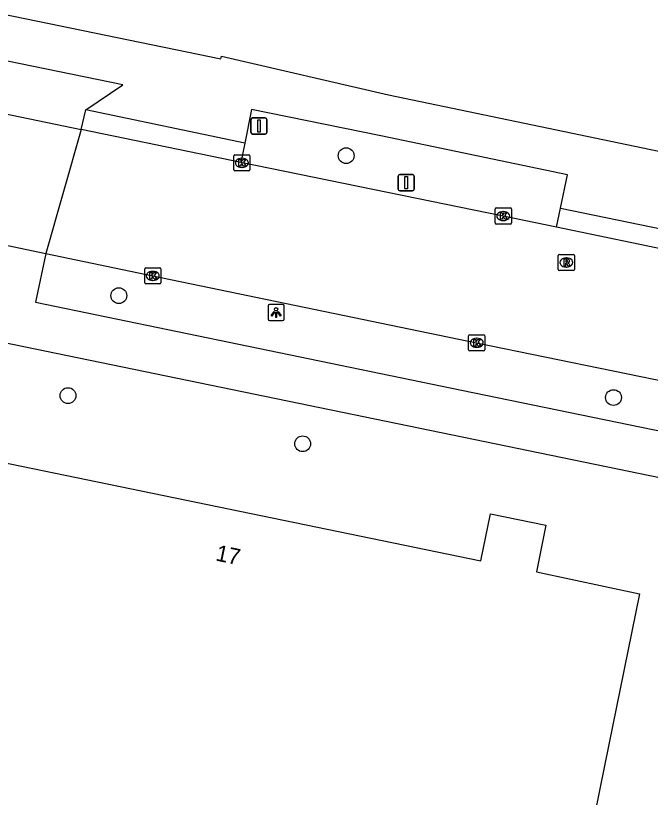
# Model space of a CAD drawing. Extents: x 157692 to 159670, y 381454 to 383289.
# Drawn here: x 158298.36 to 158337.61, y 382496.74 to 382545.08 of the extents above; entities that cross this region are included whole.
import ezdxf

# ---------------------------------------------------------------- set-up
doc = ezdxf.new("R2010")
doc.units = 0
for name, color, linetype in [('IMGEO_Boom', 7, 'Continuous'), ('IMGEO_Kolk', 7, 'Continuous'), ('IMGEO_Lichtpunt', 7, 'Continuous'), ('IMGEO_Pand', 7, 'Continuous'), ('IMGEO_Pand_nummerreeks', 7, 'Continuous'), ('IMGEO_Rijbaan_lokaal_gesloten', 7, 'Continuous'), ('IMGEO_Rioolput', 7, 'Continuous'), ('IMGEO_Verkeersbordpaal', 7, 'Continuous'), ('IMGEO_Voetpad_open', 7, 'Continuous')]:
    doc.layers.add(name, color=color, linetype=linetype)

msp = doc.modelspace()

# ---------------------------------------------------------------- linework, layer by layer
at = {"layer": 'IMGEO_Boom'}
for centre in [(158318.796, 382536.419), (158304.747, 382527.763), (158301.599, 382521.583), (158335.33, 382521.46), (158316.11, 382518.605)]:
    msp.add_circle(centre, 0.489, dxfattribs=at)
at = {"layer": 'IMGEO_Kolk'}
for p, q in [((158311.85, 382535.551), (158311.85, 382536.403)), ((158311.925, 382536.477), (158312.777, 382536.477)), ((158312.338, 382536.257), (158312.363, 382536.257)), ((158312.851, 382536.403), (158312.851, 382535.551)), ((158312.361, 382535.697), (158312.336, 382535.697)), ((158312.777, 382535.477), (158311.925, 382535.477)), ((158328.086, 382533.186), (158328.938, 382533.186)), ((158328.011, 382532.26), (158328.011, 382533.112)), ((158328.499, 382532.966), (158328.524, 382532.966)), ((158329.012, 382533.112), (158329.012, 382532.26)), ((158328.938, 382532.186), (158328.086, 382532.186)), ((158328.522, 382532.406), (158328.497, 382532.406)), ((158306.343, 382528.56), (158306.343, 382529.412)), ((158306.418, 382529.486), (158307.27, 382529.486)), ((158307.344, 382529.412), (158307.344, 382528.56)), ((158306.831, 382529.266), (158306.856, 382529.266)), ((158307.27, 382528.486), (158306.418, 382528.486)), ((158306.854, 382528.706), (158306.829, 382528.706)), ((158326.37, 382524.423), (158326.37, 382525.275)), ((158326.445, 382525.349), (158327.297, 382525.349)), ((158326.858, 382525.129), (158326.883, 382525.129)), ((158327.371, 382525.275), (158327.371, 382524.423)), ((158326.881, 382524.569), (158326.856, 382524.569)), ((158327.297, 382524.349), (158326.445, 382524.349))]:
    msp.add_line(p, q, dxfattribs=at)
for points in [[(158311.85, 382535.551), (158311.85, 382536.403)], [(158311.925, 382536.477), (158312.777, 382536.477)], [(158312.171, 382536.177), (158312.294, 382536.177), (158312.294, 382536.026), (158312.424, 382536.177), (158312.588, 382536.177), (158312.442, 382536.026), (158312.595, 382535.777), (158312.443, 382535.777), (158312.358, 382535.941), (158312.294, 382535.874), (158312.294, 382535.777), (158312.171, 382535.777), (158312.171, 382536.177)], [(158312.851, 382536.403), (158312.851, 382535.551)], [(158312.777, 382535.477), (158311.925, 382535.477)], [(158328.086, 382533.186), (158328.938, 382533.186)], [(158328.011, 382532.26), (158328.011, 382533.112)], [(158328.332, 382532.886), (158328.455, 382532.886), (158328.455, 382532.735), (158328.585, 382532.886), (158328.749, 382532.886), (158328.603, 382532.735), (158328.756, 382532.486), (158328.604, 382532.486), (158328.519, 382532.65), (158328.455, 382532.583), (158328.455, 382532.486), (158328.332, 382532.486), (158328.332, 382532.886)], [(158329.012, 382533.112), (158329.012, 382532.26)], [(158328.938, 382532.186), (158328.086, 382532.186)], [(158306.343, 382528.56), (158306.343, 382529.412)], [(158306.418, 382529.486), (158307.27, 382529.486)], [(158307.344, 382529.412), (158307.344, 382528.56)], [(158306.664, 382529.186), (158306.787, 382529.186), (158306.787, 382529.035), (158306.917, 382529.186), (158307.081, 382529.186), (158306.935, 382529.035), (158307.088, 382528.786), (158306.936, 382528.786), (158306.851, 382528.95), (158306.787, 382528.883), (158306.787, 382528.786), (158306.664, 382528.786), (158306.664, 382529.186)], [(158307.27, 382528.486), (158306.418, 382528.486)], [(158326.37, 382524.423), (158326.37, 382525.275)], [(158326.445, 382525.349), (158327.297, 382525.349)], [(158326.691, 382525.049), (158326.814, 382525.049), (158326.814, 382524.898), (158326.944, 382525.049), (158327.108, 382525.049), (158326.962, 382524.898), (158327.115, 382524.649), (158326.963, 382524.649), (158326.878, 382524.813), (158326.814, 382524.746), (158326.814, 382524.649), (158326.691, 382524.649), (158326.691, 382525.049)], [(158327.371, 382525.275), (158327.371, 382524.423)], [(158327.297, 382524.349), (158326.445, 382524.349)]]:
    msp.add_lwpolyline(points, dxfattribs=at)
for centre, start, end in [((158311.927, 382536.401), 91.552, 178.448), ((158311.927, 382536.401), 91.552, 178.448), ((158312.775, 382536.401), 1.552, 88.448), ((158312.775, 382536.401), 1.552, 88.448), ((158311.927, 382535.553), 181.552, 268.448), ((158311.927, 382535.553), 181.552, 268.448), ((158312.775, 382535.553), 271.552, 358.448), ((158312.775, 382535.553), 271.552, 358.448), ((158328.088, 382533.11), 91.552, 178.448), ((158328.088, 382533.11), 91.552, 178.448), ((158328.936, 382533.11), 1.552, 88.448), ((158328.936, 382533.11), 1.552, 88.448), ((158328.088, 382532.262), 181.552, 268.448), ((158328.088, 382532.262), 181.552, 268.448), ((158328.936, 382532.262), 271.552, 358.448), ((158328.936, 382532.262), 271.552, 358.448), ((158306.42, 382529.41), 91.552, 178.448), ((158306.42, 382529.41), 91.552, 178.448), ((158307.268, 382529.41), 1.552, 88.448), ((158307.268, 382529.41), 1.552, 88.448), ((158306.42, 382528.562), 181.552, 268.448), ((158306.42, 382528.562), 181.552, 268.448), ((158307.268, 382528.562), 271.552, 358.448), ((158307.268, 382528.562), 271.552, 358.448), ((158326.447, 382525.273), 91.552, 178.448), ((158326.447, 382525.273), 91.552, 178.448), ((158327.295, 382525.273), 1.552, 88.448), ((158327.295, 382525.273), 1.552, 88.448), ((158326.447, 382524.425), 181.552, 268.448), ((158326.447, 382524.425), 181.552, 268.448), ((158327.295, 382524.425), 271.552, 358.448), ((158327.295, 382524.425), 271.552, 358.448)]:
    msp.add_arc(centre, 0.0765, start, end, dxfattribs=at)
for centre, major_axis, ratio, start_param, end_param in [((158312.337, 382535.977), (-0.387, 0.002), 0.722429, 4.712389, 7.853982), ((158312.362, 382535.977), (-0.39, 0.002), 0.717154, 1.570796, 4.712389), ((158328.498, 382532.686), (-0.387, 0.002), 0.722429, 4.712389, 7.853982), ((158328.523, 382532.686), (-0.39, 0.002), 0.717154, 1.570796, 4.712389), ((158306.83, 382528.986), (-0.387, 0.002), 0.722429, 4.712389, 7.853982), ((158306.855, 382528.986), (-0.39, 0.002), 0.717154, 1.570796, 4.712389), ((158326.857, 382524.849), (-0.387, 0.002), 0.722429, 4.712389, 7.853982), ((158326.882, 382524.849), (-0.39, 0.002), 0.717154, 1.570796, 4.712389)]:
    msp.add_ellipse(centre, major_axis=major_axis, ratio=ratio, start_param=start_param, end_param=end_param, dxfattribs=at)
at = {"layer": 'IMGEO_Lichtpunt'}
for p, q in [((158313.969, 382527.125), (158313.969, 382526.318)), ((158313.969, 382527.125), (158313.969, 382526.318)), ((158314.871, 382527.22), (158314.063, 382527.22)), ((158314.871, 382527.22), (158314.063, 382527.22)), ((158314.965, 382526.318), (158314.965, 382527.125)), ((158314.965, 382526.318), (158314.965, 382527.125)), ((158314.063, 382526.224), (158314.871, 382526.224)), ((158314.063, 382526.224), (158314.871, 382526.224))]:
    msp.add_line(p, q, dxfattribs=at)
for points in [[(158314.343, 382526.789), (158314.382, 382526.761), (158314.194, 382526.499), (158314.156, 382526.526), (158314.343, 382526.789)], [(158314.445, 382526.741), (158314.492, 382526.741), (158314.492, 382526.419), (158314.445, 382526.419), (158314.445, 382526.741)], [(158314.555, 382526.761), (158314.593, 382526.788), (158314.78, 382526.526), (158314.741, 382526.498), (158314.555, 382526.761)]]:
    msp.add_lwpolyline(points, dxfattribs=at)
msp.add_circle((158314.468, 382526.923), 0.0994, dxfattribs=at)
for centre, start, end in [((158314.063, 382527.125), 90, 180), ((158314.063, 382527.125), 90, 180), ((158314.871, 382527.125), 0, 90), ((158314.871, 382527.125), 0, 90), ((158314.063, 382526.318), 180, 270), ((158314.063, 382526.318), 180, 270), ((158314.871, 382526.318), 270, 0), ((158314.871, 382526.318), 270, 360)]:
    msp.add_arc(centre, 0.0946, start, end, dxfattribs=at)
at = {"layer": 'IMGEO_Pand'}
msp.add_lwpolyline([(158282.608, 382497.216), (158283.179, 382500), (158286.343, 382515.416), (158287.199, 382519.584), (158327.119, 382511.361), (158327.717, 382514.268), (158331.148, 382513.575), (158330.573, 382510.691), (158336.933, 382509.322), (158335.04, 382500), (158332.399, 382486.997), (158282.608, 382497.216)], dxfattribs=at)
at = {"layer": 'IMGEO_Rijbaan_lokaal_gesloten'}
for points in [[(158285.228, 382541.605), (158302.415, 382538.043)], [(158302.415, 382538.043), (158300.233, 382530.369)], [(158312.285, 382535.999), (158311.71, 382536.116), (158302.415, 382538.043)], [(158331.802, 382531.993), (158328.512, 382532.685), (158320.449, 382534.334), (158312.285, 382535.999)], [(158290.003, 382532.509), (158300.233, 382530.369)], [(158339.525, 382530.385), (158331.802, 382531.993)], [(158300.233, 382530.369), (158306.84, 382528.987), (158326.867, 382524.85), (158347.973, 382520.508), (158348.728, 382520.358)]]:
    msp.add_lwpolyline(points, dxfattribs=at)
at = {"layer": 'IMGEO_Rioolput'}
for p, q in [((158331.986, 382530.314), (158332.838, 382530.314)), ((158331.911, 382529.388), (158331.911, 382530.24)), ((158332.399, 382530.094), (158332.424, 382530.094)), ((158332.912, 382530.24), (158332.912, 382529.388)), ((158332.838, 382529.314), (158331.986, 382529.314)), ((158332.422, 382529.534), (158332.397, 382529.534))]:
    msp.add_line(p, q, dxfattribs=at)
for points in [[(158331.986, 382530.314), (158332.838, 382530.314)], [(158331.911, 382529.388), (158331.911, 382530.24)], [(158332.5, 382530.012), (158332.248, 382530.014), (158332.248, 382529.614)], [(158332.248, 382529.614), (158332.372, 382529.614), (158332.372, 382529.776), (158332.383, 382529.776)], [(158332.426, 382529.933), (158332.372, 382529.933), (158332.372, 382529.852)], [(158332.372, 382529.852), (158332.424, 382529.852)], [(158332.912, 382530.24), (158332.912, 382529.388)], [(158332.838, 382529.314), (158331.986, 382529.314)], [(158332.43, 382529.747), (158332.501, 382529.614), (158332.641, 382529.614), (158332.576, 382529.74)]]:
    msp.add_lwpolyline(points, dxfattribs=at)
for centre, radius, start, end in [((158331.988, 382530.238), 0.0765, 91.552, 178.448), ((158331.988, 382530.238), 0.0765, 91.552, 178.448), ((158332.836, 382530.238), 0.0765, 1.552, 88.448), ((158332.836, 382530.238), 0.0765, 1.552, 88.448), ((158332.382, 382529.723), 0.0533, 26.0293, 88.6989), ((158332.408, 382530.041), 0.19, 274.7715, 282.9687), ((158332.432, 382529.837), 0.0964, 77.0061, 93.1865), ((158332.446, 382529.894), 0.0378, 276.6634, 79.6772), ((158332.499, 382529.902), 0.109, 350.3612, 89.416), ((158332.497, 382529.902), 0.112, 277.5842, 350.9817), ((158332.481, 382529.687), 0.108, 29.5134, 73.7905), ((158331.988, 382529.39), 0.0765, 181.552, 268.448), ((158331.988, 382529.39), 0.0765, 181.552, 268.448), ((158332.836, 382529.39), 0.0765, 271.552, 358.448), ((158332.836, 382529.39), 0.0765, 271.552, 358.448)]:
    msp.add_arc(centre, radius, start, end, dxfattribs=at)
for centre, major_axis, ratio, start_param, end_param in [((158332.398, 382529.814), (-0.387, 0.002), 0.722429, 4.712389, 7.853982), ((158332.423, 382529.814), (-0.39, 0.002), 0.717154, 1.570796, 4.712389)]:
    msp.add_ellipse(centre, major_axis=major_axis, ratio=ratio, start_param=start_param, end_param=end_param, dxfattribs=at)
at = {"layer": 'IMGEO_Verkeersbordpaal'}
for p, q in [((158312.909, 382537.853), (158312.909, 382538.653)), ((158312.909, 382538.653), (158312.909, 382537.853)), ((158313.009, 382538.753), (158313.799, 382538.753)), ((158313.799, 382538.753), (158313.009, 382538.753)), ((158313.899, 382538.653), (158313.899, 382537.853)), ((158313.899, 382537.853), (158313.899, 382538.653)), ((158313.799, 382537.753), (158313.009, 382537.753)), ((158313.009, 382537.753), (158313.799, 382537.753)), ((158322.014, 382534.35), (158322.014, 382535.15)), ((158322.014, 382535.15), (158322.014, 382534.35)), ((158322.114, 382535.25), (158322.904, 382535.25)), ((158322.904, 382535.25), (158322.114, 382535.25)), ((158323.004, 382535.15), (158323.004, 382534.35)), ((158323.004, 382534.35), (158323.004, 382535.15)), ((158322.904, 382534.25), (158322.114, 382534.25)), ((158322.114, 382534.25), (158322.904, 382534.25))]:
    msp.add_line(p, q, dxfattribs=at)
for points in [[(158313.329, 382538.628), (158313.479, 382538.628), (158313.479, 382537.878), (158313.329, 382537.878), (158313.329, 382538.628)], [(158322.434, 382535.125), (158322.584, 382535.125), (158322.584, 382534.375), (158322.434, 382534.375), (158322.434, 382535.125)]]:
    msp.add_lwpolyline(points, dxfattribs=at)
for centre, start, end in [((158313.009, 382538.653), 90, 180), ((158313.009, 382538.653), 90, 180), ((158313.799, 382538.653), 0, 90), ((158313.799, 382538.653), 360, 90), ((158313.009, 382537.853), 180, 270), ((158313.009, 382537.853), 180, 270), ((158313.799, 382537.853), 270, 0), ((158313.799, 382537.853), 270, 0), ((158322.114, 382535.15), 90, 180), ((158322.114, 382535.15), 90, 180), ((158322.904, 382535.15), 0, 90), ((158322.904, 382535.15), 360, 90), ((158322.114, 382534.35), 180, 270), ((158322.114, 382534.35), 180, 270), ((158322.904, 382534.35), 270, 0), ((158322.904, 382534.35), 270, 0)]:
    msp.add_arc(centre, 0.1, start, end, dxfattribs=at)
at = {"layer": 'IMGEO_Voetpad_open'}
for points in [[(158195.722, 382566.191), (158274.782, 382549.891), (158311.051, 382542.412), (158311.095, 382542.581), (158321.419, 382540.176), (158391.337, 382525.614), (158405.273, 382522.711), (158421.57, 382519.396), (158421.623, 382519.691), (158430.232, 382517.917), (158430.22, 382517.771), (158448.226, 382514.066), (158448.261, 382514.179), (158456.419, 382512.52), (158477.322, 382508.223), (158500, 382503.578), (158504.177, 382502.734)], [(158302.697, 382539.25), (158304.989, 382540.809), (158285.883, 382544.714), (158285.48, 382542.785)], [(158302.415, 382538.043), (158302.697, 382539.25)], [(158312.529, 382537.196), (158302.697, 382539.25)], [(158332.059, 382533.173), (158332.478, 382535.245), (158320.944, 382537.65), (158312.955, 382539.284), (158312.529, 382537.196)], [(158312.529, 382537.196), (158312.285, 382535.999)], [(158331.802, 382531.993), (158332.059, 382533.173)], [(158332.059, 382533.173), (158339.75, 382531.581)], [(158300.233, 382530.369), (158299.595, 382527.37), (158325.936, 382521.917), (158348.088, 382517.356), (158348.451, 382519.172)], [(158360.284, 382511.928), (158352.753, 382513.48), (158347.768, 382514.508), (158288.641, 382526.697), (158286.766, 382527.066)]]:
    msp.add_lwpolyline(points, dxfattribs=at)

# ---------------------------------------------------------------- texts
at = {"layer": 'IMGEO_Pand_nummerreeks'}
msp.add_text('17', height=1, rotation=348.3413, dxfattribs=at).set_placement((158310.683, 382511.39))

doc.saveas('drawing.dxf')
